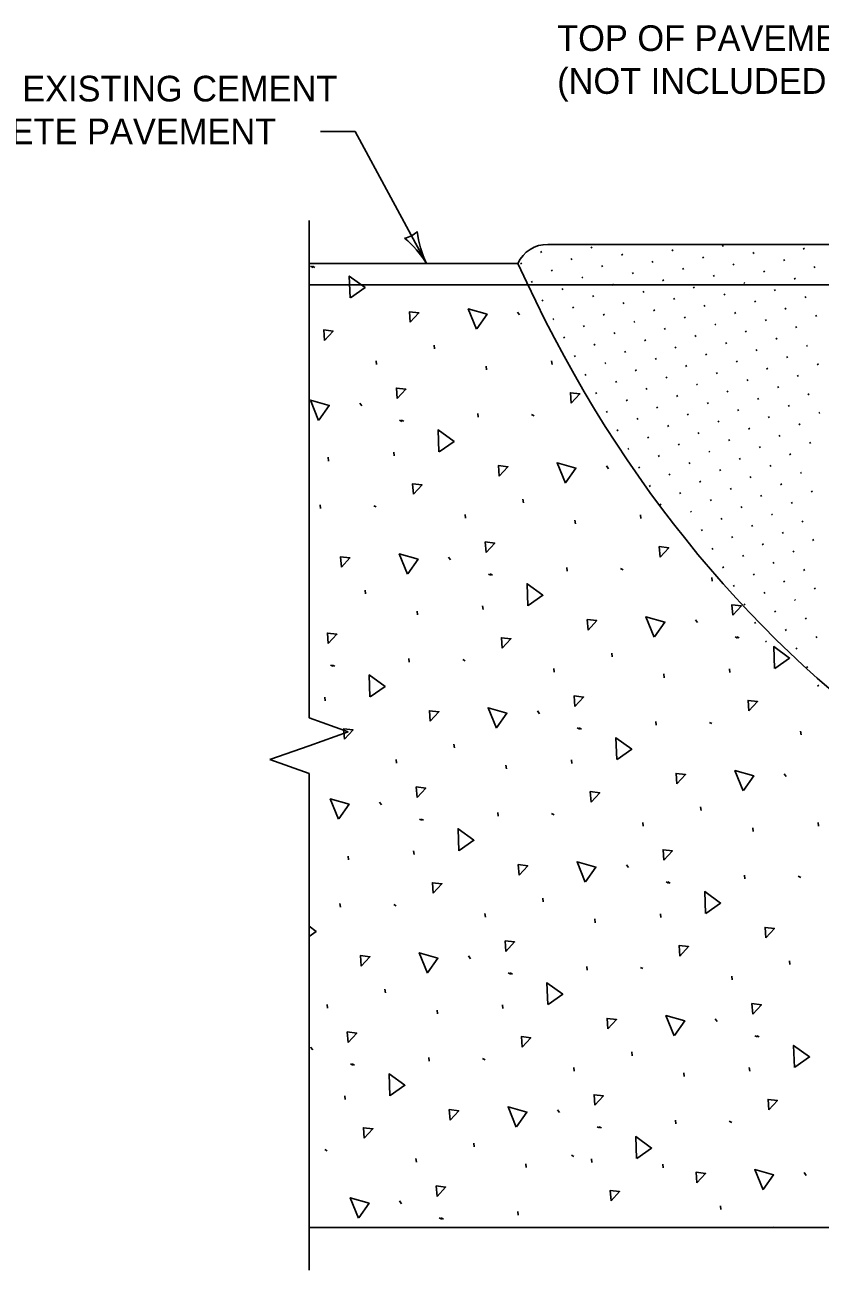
# Model space of a CAD drawing. Extents: x 49991.4 to 50021, y 49987.6 to 50011.4.
# Drawn here: x 50001.317 to 50003.173, y 49992.483 to 49995.39 of the extents above; entities that cross this region are included whole.
import ezdxf

# ---------------------------------------------------------------- set-up
doc = ezdxf.new("R2010")
doc.units = 0
for name, color, linetype in [('Level 1', 7, 'Continuous'), ('Level 2', 7, 'Continuous'), ('Level 3', 7, 'Continuous'), ('Level 4', 7, 'Continuous'), ('Level 6', 7, 'Continuous')]:
    doc.layers.add(name, color=color, linetype=linetype)

msp = doc.modelspace()

# ---------------------------------------------------------------- linework, layer by layer
at = {"layer": 'Level 1'}
for p, q in [((50002.5376, 49994.8772), (50004.5362, 49994.8772)), ((50002.4679, 49994.8328), (50001.9803, 49994.8328)), ((50008.0315, 49994.7828), (50001.9803, 49994.7828))]:
    msp.add_line(p, q, dxfattribs=at)
msp.add_lwpolyline([(50001.9803, 49992.5827), (50004.606, 49992.5827), (50014.3713, 49992.5827)], dxfattribs=at)
msp.add_arc((50002.5362, 49994.8027), 0.0746, 88.8654, 156.1576, dxfattribs=at)
msp.add_ellipse((50004.6259, 49996.2377), major_axis=(0, -2.952), ratio=0.83118, start_param=5.208402, end_param=6.283185, dxfattribs=at)
at = {"layer": 'Level 3'}
for p, q in [((50002.0877, 49995.141), (50002.0069, 49995.141)), ((50002.0877, 49995.141), (50002.2544, 49994.8328)), ((50002.9447, 49994.8729), (50002.9477, 49994.8747)), ((50002.5203, 49994.8588), (50002.5233, 49994.8606)), ((50002.638, 49994.869), (50002.641, 49994.8708)), ((50002.7093, 49994.8525), (50002.7123, 49994.8542)), ((50002.827, 49994.8627), (50002.83, 49994.8645)), ((50002.8983, 49994.8462), (50002.9014, 49994.8479)), ((50003.016, 49994.8564), (50003.019, 49994.8581)), ((50003.1337, 49994.8666), (50003.1367, 49994.8683)), ((50002.474, 49994.8321), (50002.477, 49994.8338)), ((50002.5453, 49994.8155), (50002.5483, 49994.8173)), ((50002.5916, 49994.8423), (50002.5947, 49994.844)), ((50002.663, 49994.8257), (50002.666, 49994.8275)), ((50002.7806, 49994.836), (50002.7837, 49994.8377)), ((50002.852, 49994.8194), (50002.855, 49994.8212)), ((50002.9697, 49994.8296), (50002.9727, 49994.8314)), ((50003.0873, 49994.8398), (50003.0904, 49994.8416)), ((50003.1587, 49994.8233), (50003.1617, 49994.825)), ((50002.499, 49994.7888), (50002.502, 49994.7905)), ((50002.6166, 49994.799), (50002.6197, 49994.8007)), ((50002.7343, 49994.8092), (50002.7373, 49994.8109)), ((50002.8056, 49994.7926), (50002.8087, 49994.7944)), ((50002.9233, 49994.8029), (50002.9264, 49994.8046)), ((50002.9947, 49994.7863), (50002.9977, 49994.7881)), ((50003.041, 49994.8131), (50003.044, 49994.8148)), ((50003.1123, 49994.7965), (50003.1154, 49994.7983)), ((50002.5703, 49994.7722), (50002.5733, 49994.774)), ((50002.688, 49994.7824), (50002.691, 49994.7842)), ((50002.7593, 49994.7659), (50002.7623, 49994.7676)), ((50002.877, 49994.7761), (50002.88, 49994.7779)), ((50002.9483, 49994.7596), (50002.9514, 49994.7613)), ((50003.066, 49994.7698), (50003.069, 49994.7715)), ((50002.524, 49994.7455), (50002.527, 49994.7472)), ((50002.5953, 49994.7289), (50002.5983, 49994.7307)), ((50002.6416, 49994.7557), (50002.6447, 49994.7574)), ((50002.713, 49994.7391), (50002.716, 49994.7409)), ((50002.8306, 49994.7493), (50002.8337, 49994.7511)), ((50002.902, 49994.7328), (50002.905, 49994.7346)), ((50003.0197, 49994.743), (50003.0227, 49994.7448)), ((50003.1373, 49994.7532), (50003.1404, 49994.755)), ((50002.549, 49994.7022), (50002.552, 49994.7039)), ((50002.6666, 49994.7124), (50002.6697, 49994.7141)), ((50002.7843, 49994.7226), (50002.7873, 49994.7243)), ((50002.8556, 49994.706), (50002.8587, 49994.7078)), ((50002.9733, 49994.7163), (50002.9764, 49994.718)), ((50003.0447, 49994.6997), (50003.0477, 49994.7015)), ((50003.091, 49994.7265), (50003.094, 49994.7282)), ((50003.1623, 49994.7099), (50003.1654, 49994.7117)), ((50002.6203, 49994.6856), (50002.6233, 49994.6874)), ((50002.6916, 49994.6691), (50002.6947, 49994.6708)), ((50002.738, 49994.6958), (50002.741, 49994.6976)), ((50002.8093, 49994.6793), (50002.8123, 49994.681)), ((50002.927, 49994.6895), (50002.93, 49994.6912)), ((50002.9983, 49994.673), (50003.0014, 49994.6747)), ((50003.116, 49994.6832), (50003.119, 49994.6849)), ((50002.574, 49994.6589), (50002.577, 49994.6606)), ((50002.6453, 49994.6423), (50002.6483, 49994.6441)), ((50002.763, 49994.6525), (50002.766, 49994.6543)), ((50002.8806, 49994.6627), (50002.8837, 49994.6645)), ((50002.952, 49994.6462), (50002.955, 49994.6479)), ((50003.0697, 49994.6564), (50003.0727, 49994.6582)), ((50003.141, 49994.6399), (50003.144, 49994.6416)), ((50002.599, 49994.6156), (50002.602, 49994.6173)), ((50002.7166, 49994.6258), (50002.7197, 49994.6275)), ((50002.8343, 49994.636), (50002.8373, 49994.6377)), ((50002.9056, 49994.6194), (50002.9087, 49994.6212)), ((50003.0233, 49994.6296), (50003.0264, 49994.6314)), ((50003.0947, 49994.6131), (50003.0977, 49994.6149)), ((50002.6703, 49994.599), (50002.6733, 49994.6008)), ((50002.7416, 49994.5825), (50002.7447, 49994.5842)), ((50002.788, 49994.6092), (50002.791, 49994.611)), ((50002.8593, 49994.5927), (50002.8623, 49994.5944)), ((50002.977, 49994.6029), (50002.98, 49994.6046)), ((50003.0483, 49994.5863), (50003.0514, 49994.5881)), ((50003.166, 49994.5966), (50003.169, 49994.5983)), ((50002.624, 49994.5723), (50002.627, 49994.574)), ((50002.6953, 49994.5557), (50002.6983, 49994.5575)), ((50002.813, 49994.5659), (50002.816, 49994.5677)), ((50002.9306, 49994.5761), (50002.9337, 49994.5779)), ((50003.002, 49994.5596), (50003.005, 49994.5613)), ((50003.1197, 49994.5698), (50003.1227, 49994.5716)), ((50002.649, 49994.529), (50002.652, 49994.5307)), ((50002.7666, 49994.5392), (50002.7697, 49994.5409)), ((50002.8843, 49994.5494), (50002.8873, 49994.5511)), ((50002.9556, 49994.5328), (50002.9587, 49994.5346)), ((50003.0733, 49994.543), (50003.0764, 49994.5448)), ((50003.1447, 49994.5265), (50003.1477, 49994.5282)), ((50002.7203, 49994.5124), (50002.7233, 49994.5142)), ((50002.7916, 49994.4959), (50002.7947, 49994.4976)), ((50002.838, 49994.5226), (50002.841, 49994.5244)), ((50002.9093, 49994.5061), (50002.9123, 49994.5078)), ((50003.027, 49994.5163), (50003.03, 49994.518)), ((50003.0983, 49994.4997), (50003.1014, 49994.5015)), ((50002.674, 49994.4857), (50002.677, 49994.4874)), ((50002.7453, 49994.4691), (50002.7483, 49994.4709)), ((50002.863, 49994.4793), (50002.866, 49994.4811)), ((50002.9806, 49994.4895), (50002.9837, 49994.4913)), ((50003.052, 49994.473), (50003.055, 49994.4747)), ((50003.1697, 49994.4832), (50003.1727, 49994.4849)), ((50002.699, 49994.4424), (50002.702, 49994.4441)), ((50002.8166, 49994.4526), (50002.8197, 49994.4543)), ((50002.9343, 49994.4628), (50002.9373, 49994.4645)), ((50003.0056, 49994.4462), (50003.0087, 49994.448)), ((50003.1233, 49994.4564), (50003.1264, 49994.4582)), ((50002.7703, 49994.4258), (50002.7733, 49994.4276)), ((50002.8416, 49994.4093), (50002.8447, 49994.411)), ((50002.888, 49994.436), (50002.891, 49994.4378)), ((50002.9593, 49994.4195), (50002.9623, 49994.4212)), ((50003.077, 49994.4297), (50003.08, 49994.4314)), ((50003.1483, 49994.4131), (50003.1514, 49994.4149)), ((50002.724, 49994.3991), (50002.727, 49994.4008)), ((50002.7953, 49994.3825), (50002.7983, 49994.3843)), ((50002.913, 49994.3927), (50002.916, 49994.3945)), ((50003.0306, 49994.4029), (50003.0337, 49994.4047)), ((50003.102, 49994.3864), (50003.105, 49994.3881)), ((50002.749, 49994.3558), (50002.752, 49994.3575)), ((50002.8666, 49994.366), (50002.8697, 49994.3677)), ((50002.938, 49994.3494), (50002.941, 49994.3512)), ((50002.9843, 49994.3762), (50002.9873, 49994.3779)), ((50003.0556, 49994.3596), (50003.0587, 49994.3614)), ((50002.8203, 49994.3392), (50002.8233, 49994.341)), ((50002.8916, 49994.3227), (50002.8947, 49994.3244)), ((50003.0093, 49994.3329), (50003.0123, 49994.3346)), ((50003.127, 49994.3431), (50003.13, 49994.3448)), ((50002.774, 49994.3125), (50002.777, 49994.3142)), ((50002.8453, 49994.2959), (50002.8483, 49994.2977)), ((50002.963, 49994.3061), (50002.966, 49994.3079)), ((50003.0806, 49994.3163), (50003.0837, 49994.3181)), ((50003.152, 49994.2998), (50003.155, 49994.3015)), ((50002.799, 49994.2692), (50002.802, 49994.2709)), ((50002.9166, 49994.2794), (50002.9197, 49994.2811)), ((50002.988, 49994.2628), (50002.991, 49994.2646)), ((50003.0343, 49994.2896), (50003.0373, 49994.2913)), ((50003.1056, 49994.273), (50003.1087, 49994.2748)), ((50002.8703, 49994.2526), (50002.8733, 49994.2544)), ((50002.9416, 49994.2361), (50002.9447, 49994.2378)), ((50003.0593, 49994.2463), (50003.0623, 49994.248)), ((50002.8953, 49994.2093), (50002.8983, 49994.2111)), ((50003.013, 49994.2195), (50003.016, 49994.2213)), ((50003.1306, 49994.2297), (50003.1337, 49994.2315)), ((50002.9666, 49994.1928), (50002.9697, 49994.1945)), ((50003.038, 49994.1762), (50003.041, 49994.178)), ((50003.0843, 49994.203), (50003.0873, 49994.2047)), ((50003.1556, 49994.1864), (50003.1587, 49994.1882)), ((50002.9203, 49994.166), (50002.9233, 49994.1678)), ((50002.9916, 49994.1495), (50002.9947, 49994.1512)), ((50003.1093, 49994.1597), (50003.1123, 49994.1614)), ((50002.9453, 49994.1227), (50002.9483, 49994.1245)), ((50003.063, 49994.1329), (50003.066, 49994.1347)), ((50003.0166, 49994.1062), (50003.0197, 49994.1079)), ((50003.088, 49994.0896), (50003.091, 49994.0914)), ((50003.1343, 49994.1164), (50003.1373, 49994.1181)), ((50002.9703, 49994.0794), (50002.9733, 49994.0812)), ((50003.0416, 49994.0629), (50003.0447, 49994.0646)), ((50003.1593, 49994.0731), (50003.1623, 49994.0748)), ((50002.9953, 49994.0361), (50002.9983, 49994.0379)), ((50003.113, 49994.0463), (50003.116, 49994.0481)), ((50003.0666, 49994.0196), (50003.0697, 49994.0213)), ((50003.138, 49994.003), (50003.141, 49994.0048)), ((50003.0203, 49993.9928), (50003.0233, 49993.9946)), ((50003.0916, 49993.9763), (50003.0947, 49993.978)), ((50003.0453, 49993.9495), (50003.0483, 49993.9513)), ((50003.163, 49993.9597), (50003.166, 49993.9615)), ((50003.1166, 49993.933), (50003.1197, 49993.9347)), ((50003.1416, 49993.8897), (50003.1447, 49993.8914)), ((50003.1666, 49993.8464), (50003.1697, 49993.8481))]:
    msp.add_line(p, q, dxfattribs=at)
for centre, radius, start, end in [((50002.1934, 49994.9456), 0.0548, 280.5446, 316.267), ((50002.4541, 49994.9304), 0.2223, 185.8618, 206.0453), ((50002.0552, 49994.712), 0.233, 31.2331, 50.483)]:
    msp.add_arc(centre, radius, start, end, dxfattribs=at)
at = {"layer": 'Level 4'}
for p, q in [((50001.9841, 49994.8264), (50001.9898, 49994.8236)), ((50001.9882, 49994.8264), (50001.9939, 49994.8236)), ((50002.467, 49994.7194), (50002.4718, 49994.713)), ((50002.273, 49994.6332), (50002.2721, 49994.6419)), ((50002.1379, 49994.5972), (50002.137, 49994.6059)), ((50002.3945, 49994.5844), (50002.3936, 49994.5931)), ((50002.5474, 49994.5967), (50002.5465, 49994.6053)), ((50002.0987, 49994.5068), (50002.1034, 49994.5003)), ((50002.1915, 49994.4672), (50002.1972, 49994.4643)), ((50002.1956, 49994.4672), (50002.2013, 49994.4644)), ((50002.3754, 49994.4737), (50002.3744, 49994.4824)), ((50002.4999, 49994.48), (50002.5057, 49994.4772)), ((50002.0261, 49994.3717), (50002.0252, 49994.3804)), ((50002.179, 49994.384), (50002.1781, 49994.3927)), ((50002.6744, 49994.3602), (50002.6792, 49994.3537)), ((50002.007, 49994.261), (50002.0061, 49994.2697)), ((50002.1315, 49994.2673), (50002.1373, 49994.2645)), ((50002.4805, 49994.274), (50002.4795, 49994.2827)), ((50002.3454, 49994.238), (50002.3444, 49994.2467)), ((50002.7548, 49994.2374), (50002.7539, 49994.2461)), ((50002.6019, 49994.2252), (50002.601, 49994.2339)), ((50002.3061, 49994.1475), (50002.3108, 49994.141)), ((50002.5828, 49994.1145), (50002.5819, 49994.1232)), ((50002.7073, 49994.1208), (50002.7131, 49994.1179)), ((50002.3989, 49994.1079), (50002.4046, 49994.1051)), ((50002.403, 49994.108), (50002.4087, 49994.1051)), ((50002.9211, 49994.0914), (50002.9202, 49994.1001)), ((50002.1121, 49994.0613), (50002.1111, 49994.07)), ((50002.3864, 49994.0247), (50002.3855, 49994.0334)), ((50002.2336, 49994.0125), (50002.2326, 49994.0212)), ((50002.8819, 49994.001), (50002.8866, 49993.9945)), ((50002.9747, 49993.9614), (50002.9804, 49993.9585)), ((50002.9788, 49993.9614), (50002.9845, 49993.9586)), ((50002.6879, 49993.9147), (50002.6869, 49993.9234)), ((50002.0305, 49993.8952), (50002.0363, 49993.8924)), ((50002.0346, 49993.8953), (50002.0403, 49993.8924)), ((50002.2144, 49993.9018), (50002.2135, 49993.9105)), ((50002.3389, 49993.9081), (50002.3447, 49993.9053)), ((50002.5528, 49993.8788), (50002.5518, 49993.8875)), ((50002.9622, 49993.8782), (50002.9613, 49993.8869)), ((50002.8093, 49993.8659), (50002.8084, 49993.8746)), ((50002.0181, 49993.812), (50002.0171, 49993.8207)), ((50002.5135, 49993.7883), (50002.5182, 49993.7818)), ((50002.6063, 49993.7487), (50002.6121, 49993.7459)), ((50002.6104, 49993.7487), (50002.6161, 49993.7459)), ((50002.7902, 49993.7553), (50002.7893, 49993.764)), ((50002.9147, 49993.7615), (50002.9205, 49993.7587)), ((50003.1286, 49993.7322), (50003.1276, 49993.7409)), ((50002.3195, 49993.702), (50002.3186, 49993.7107)), ((50002.1844, 49993.6661), (50002.1835, 49993.6748)), ((50002.441, 49993.6532), (50002.44, 49993.6619)), ((50002.5938, 49993.6655), (50002.5929, 49993.6742)), ((50003.0893, 49993.6417), (50003.094, 49993.6352)), ((50002.1451, 49993.5756), (50002.1498, 49993.5691)), ((50002.4218, 49993.5426), (50002.4209, 49993.5513)), ((50002.5463, 49993.5489), (50002.5521, 49993.546)), ((50002.8953, 49993.5555), (50002.8943, 49993.5642)), ((50002.2379, 49993.536), (50002.2437, 49993.5332)), ((50002.242, 49993.536), (50002.2478, 49993.5332)), ((50002.7602, 49993.5195), (50002.7592, 49993.5282)), ((50003.0168, 49993.5067), (50003.0158, 49993.5154)), ((50003.1696, 49993.5189), (50003.1687, 49993.5276)), ((50002.2255, 49993.4528), (50002.2245, 49993.4615)), ((50002.0726, 49993.4405), (50002.0717, 49993.4492)), ((50002.7209, 49993.429), (50002.7256, 49993.4226)), ((50002.9976, 49993.396), (50002.9967, 49993.4047)), ((50003.1221, 49993.4023), (50003.1279, 49993.3995)), ((50002.8137, 49993.3895), (50002.8195, 49993.3866)), ((50002.8178, 49993.3895), (50002.8235, 49993.3866)), ((50002.0534, 49993.3299), (50002.0525, 49993.3386)), ((50002.178, 49993.3362), (50002.1837, 49993.3333)), ((50002.5269, 49993.3428), (50002.526, 49993.3515)), ((50002.3918, 49993.3068), (50002.3909, 49993.3155)), ((50002.8013, 49993.3062), (50002.8003, 49993.3149)), ((50002.6484, 49993.294), (50002.6474, 49993.3027)), ((50002.3525, 49993.2163), (50002.3573, 49993.2099)), ((50002.6292, 49993.1833), (50002.6283, 49993.192)), ((50002.7537, 49993.1896), (50002.7595, 49993.1868)), ((50003.1027, 49993.1962), (50003.1018, 49993.2049)), ((50002.4453, 49993.1768), (50002.4511, 49993.1739)), ((50002.4494, 49993.1768), (50002.4552, 49993.1739)), ((50002.9676, 49993.1603), (50002.9667, 49993.169)), ((50002.1585, 49993.1301), (50002.1576, 49993.1388)), ((50002.0234, 49993.0941), (50002.0225, 49993.1028)), ((50002.4329, 49993.0936), (50002.4319, 49993.1023)), ((50002.28, 49993.0813), (50002.2791, 49993.09)), ((50002.9283, 49993.0698), (50002.933, 49993.0633)), ((50003.0211, 49993.0302), (50003.0269, 49993.0274)), ((50003.0252, 49993.0302), (50003.031, 49993.0274)), ((50001.9841, 49993.0037), (50001.9889, 49992.9972)), ((50002.7343, 49992.9835), (50002.7334, 49992.9922)), ((50002.0769, 49992.9641), (50002.0827, 49992.9612)), ((50002.081, 49992.9641), (50002.0868, 49992.9613)), ((50002.2608, 49992.9706), (50002.2599, 49992.9793)), ((50002.3854, 49992.9769), (50002.3911, 49992.9741)), ((50002.5992, 49992.9476), (50002.5983, 49992.9563)), ((50003.0087, 49992.947), (50003.0077, 49992.9557)), ((50002.8558, 49992.9347), (50002.8549, 49992.9434)), ((50002.0645, 49992.8809), (50002.0636, 49992.8896)), ((50002.5599, 49992.8571), (50002.5647, 49992.8506)), ((50002.6527, 49992.8175), (50002.6585, 49992.8147)), ((50002.6568, 49992.8175), (50002.6626, 49992.8147)), ((50002.8366, 49992.8241), (50002.8357, 49992.8328)), ((50002.9612, 49992.8304), (50002.9669, 49992.8275)), ((50002.017, 49992.7642), (50002.0227, 49992.7614)), ((50002.3659, 49992.7709), (50002.365, 49992.7796)), ((50002.2308, 49992.7349), (50002.2299, 49992.7436)), ((50002.4874, 49992.7221), (50002.4865, 49992.7308)), ((50002.5928, 49992.7509), (50002.5985, 49992.748)), ((50002.6403, 49992.7343), (50002.6394, 49992.743)), ((50002.8066, 49992.7216), (50002.8057, 49992.7303)), ((50003.1357, 49992.7106), (50003.1405, 49992.7041)), ((50002.1915, 49992.6444), (50002.1963, 49992.6379)), ((50002.4682, 49992.6114), (50002.4673, 49992.6201)), ((50002.9417, 49992.6243), (50002.9408, 49992.633)), ((50002.2844, 49992.6048), (50002.2901, 49992.602)), ((50002.2884, 49992.6049), (50002.2942, 49992.602)), ((50003.0624, 49992.5827), (50003.0623, 49992.5842))]:
    msp.add_line(p, q, dxfattribs=at)
for points in [[(50002.0761, 49994.7523), (50002.0742, 49994.8035), (50002.1113, 49994.7767), (50002.0769, 49994.7527)], [(50002.2167, 49994.6956), (50002.2149, 49994.7201), (50002.2369, 49994.7175), (50002.2167, 49994.6956)], [(50002.3712, 49994.6793), (50002.3519, 49994.7267), (50002.3959, 49994.7142), (50002.3718, 49994.6799)], [(50002.0164, 49994.6532), (50002.0145, 49994.6778), (50002.0366, 49994.6751), (50002.0164, 49994.6532)], [(50002.1861, 49994.5174), (50002.1842, 49994.5419), (50002.2063, 49994.5393), (50002.1861, 49994.5174)], [(50002.5922, 49994.5066), (50002.5903, 49994.5312), (50002.6124, 49994.5285), (50002.5922, 49994.5066)], [(50002.0028, 49994.4666), (50001.9835, 49994.514), (50002.0275, 49994.5015), (50002.0034, 49994.4672)], [(50002.2835, 49994.393), (50002.2817, 49994.4442), (50002.3187, 49994.4174), (50002.2843, 49994.3935)], [(50002.4241, 49994.3363), (50002.4223, 49994.3609), (50002.4443, 49994.3582), (50002.4241, 49994.3363)], [(50002.5786, 49994.32), (50002.5593, 49994.3675), (50002.6033, 49994.355), (50002.5792, 49994.3207)], [(50002.2238, 49994.294), (50002.2219, 49994.3185), (50002.244, 49994.3159), (50002.2238, 49994.294)], [(50002.3935, 49994.1581), (50002.3916, 49994.1827), (50002.4137, 49994.18), (50002.3935, 49994.1581)], [(50002.0558, 49994.1236), (50002.0539, 49994.1482), (50002.0759, 49994.1455), (50002.0558, 49994.1236)], [(50002.2102, 49994.1073), (50002.1909, 49994.1548), (50002.2349, 49994.1423), (50002.2108, 49994.108)], [(50002.7996, 49994.1474), (50002.7977, 49994.172), (50002.8198, 49994.1693), (50002.7996, 49994.1474)], [(50002.4909, 49994.0338), (50002.4891, 49994.085), (50002.5261, 49994.0582), (50002.4917, 49994.0342)], [(50002.9693, 49994.0116), (50002.9674, 49994.0361), (50002.9895, 49994.0335), (50002.9693, 49994.0116)], [(50002.786, 49993.9608), (50002.7667, 49994.0083), (50002.8107, 49993.9957), (50002.7866, 49993.9615)], [(50002.6316, 49993.9771), (50002.6297, 49994.0016), (50002.6517, 49993.999), (50002.6316, 49993.9771)], [(50002.0251, 49993.9455), (50002.0233, 49993.97), (50002.0453, 49993.9673), (50002.0251, 49993.9455)], [(50002.4312, 49993.9347), (50002.4294, 49993.9593), (50002.4514, 49993.9566), (50002.4312, 49993.9347)], [(50003.0667, 49993.8872), (50003.0649, 49993.9384), (50003.1019, 49993.9116), (50003.0675, 49993.8877)], [(50002.1226, 49993.8211), (50002.1207, 49993.8723), (50002.1577, 49993.8455), (50002.1233, 49993.8215)], [(50002.6009, 49993.7989), (50002.599, 49993.8235), (50002.6211, 49993.8208), (50002.6009, 49993.7989)], [(50003.007, 49993.7882), (50003.0051, 49993.8127), (50003.0272, 49993.8101), (50003.007, 49993.7882)], [(50002.2632, 49993.7644), (50002.2613, 49993.7889), (50002.2833, 49993.7863), (50002.2632, 49993.7644)], [(50002.4176, 49993.7481), (50002.3983, 49993.7956), (50002.4423, 49993.783), (50002.4182, 49993.7488)], [(50002.0628, 49993.722), (50002.061, 49993.7466), (50002.083, 49993.7439), (50002.0628, 49993.722)], [(50002.6983, 49993.6746), (50002.6965, 49993.7258), (50002.7335, 49993.6989), (50002.6991, 49993.675)], [(50002.839, 49993.6178), (50002.8371, 49993.6424), (50002.8591, 49993.6397), (50002.839, 49993.6178)], [(50002.9934, 49993.6015), (50002.9741, 49993.649), (50003.0181, 49993.6365), (50002.994, 49993.6022)], [(50002.2325, 49993.5862), (50002.2307, 49993.6108), (50002.2527, 49993.6081), (50002.2325, 49993.5862)], [(50002.6386, 49993.5755), (50002.6368, 49993.6), (50002.6588, 49993.5974), (50002.6386, 49993.5755)], [(50002.0492, 49993.5354), (50002.03, 49993.5829), (50002.0739, 49993.5703), (50002.0498, 49993.5361)], [(50002.33, 49993.4619), (50002.3281, 49993.5131), (50002.3651, 49993.4863), (50002.3307, 49993.4623)], [(50002.8083, 49993.4397), (50002.8065, 49993.4642), (50002.8285, 49993.4616), (50002.8083, 49993.4397)], [(50002.4706, 49993.4051), (50002.4687, 49993.4297), (50002.4907, 49993.427), (50002.4706, 49993.4051)], [(50002.625, 49993.3888), (50002.6058, 49993.4363), (50002.6497, 49993.4238), (50002.6256, 49993.3895)], [(50002.2702, 49993.3628), (50002.2684, 49993.3873), (50002.2904, 49993.3847), (50002.2702, 49993.3628)], [(50002.9058, 49993.3153), (50002.9039, 49993.3665), (50002.9409, 49993.3397), (50002.9065, 49993.3158)], [(50001.9803, 49993.2855), (50001.9967, 49993.2736), (50001.9803, 49993.2621)], [(50003.0464, 49993.2586), (50003.0445, 49993.2831), (50003.0665, 49993.2805), (50003.0464, 49993.2586)], [(50002.4399, 49993.227), (50002.4381, 49993.2515), (50002.4601, 49993.2489), (50002.4399, 49993.227)], [(50002.2567, 49993.1762), (50002.2374, 49993.2236), (50002.2813, 49993.2111), (50002.2572, 49993.1768)], [(50002.846, 49993.2162), (50002.8442, 49993.2408), (50002.8662, 49993.2381), (50002.846, 49993.2162)], [(50002.1022, 49993.1925), (50002.1003, 49993.217), (50002.1224, 49993.2144), (50002.1022, 49993.1925)], [(50002.5374, 49993.1026), (50002.5355, 49993.1538), (50002.5725, 49993.127), (50002.5381, 49993.1031)], [(50003.0157, 49993.0804), (50003.0139, 49993.105), (50003.0359, 49993.1023), (50003.0157, 49993.0804)], [(50002.8324, 49993.0296), (50002.8132, 49993.0771), (50002.8571, 49993.0645), (50002.833, 49993.0303)], [(50002.678, 49993.0459), (50002.6761, 49993.0705), (50002.6981, 49993.0678), (50002.678, 49993.0459)], [(50002.0716, 49993.0143), (50002.0697, 49993.0388), (50002.0917, 49993.0362), (50002.0716, 49993.0143)], [(50002.4777, 49993.0035), (50002.4758, 49993.0281), (50002.4978, 49993.0254), (50002.4777, 49993.0035)], [(50003.1132, 49992.9561), (50003.1113, 49993.0073), (50003.1483, 49992.9805), (50003.1139, 49992.9565)], [(50002.169, 49992.8899), (50002.1671, 49992.9411), (50002.2041, 49992.9143), (50002.1698, 49992.8904)], [(50002.6473, 49992.8677), (50002.6455, 49992.8923), (50002.6675, 49992.8896), (50002.6473, 49992.8677)], [(50003.0534, 49992.857), (50003.0516, 49992.8815), (50003.0736, 49992.8789), (50003.0534, 49992.857)], [(50002.3096, 49992.8332), (50002.3077, 49992.8578), (50002.3298, 49992.8551), (50002.3096, 49992.8332)], [(50002.4641, 49992.8169), (50002.4448, 49992.8644), (50002.4887, 49992.8519), (50002.4646, 49992.8176)], [(50002.1093, 49992.7909), (50002.1074, 49992.8154), (50002.1294, 49992.8128), (50002.1093, 49992.7909)], [(50002.7448, 49992.7434), (50002.7429, 49992.7946), (50002.7799, 49992.7678), (50002.7455, 49992.7438)], [(50002.8854, 49992.6867), (50002.8835, 49992.7112), (50002.9056, 49992.7086), (50002.8854, 49992.6867)], [(50003.0399, 49992.6704), (50003.0206, 49992.7178), (50003.0645, 49992.7053), (50003.0404, 49992.671)], [(50002.279, 49992.655), (50002.2771, 49992.6796), (50002.2991, 49992.6769), (50002.279, 49992.655)], [(50002.6851, 49992.6443), (50002.6832, 49992.6689), (50002.7052, 49992.6662), (50002.6851, 49992.6443)], [(50002.0957, 49992.6042), (50002.0764, 49992.6517), (50002.1204, 49992.6392), (50002.0962, 49992.6049)]]:
    msp.add_lwpolyline(points, dxfattribs=at)
at = {"layer": 'Level 6'}
for p, q in [((50001.9803, 49994.9331), (50001.9803, 49993.7718)), ((50002.0717, 49993.7394), (50001.9803, 49993.7718)), ((50002.0717, 49993.7394), (50001.9803, 49993.707)), ((50001.9803, 49993.707), (50001.8889, 49993.6746)), ((50001.9803, 49993.6422), (50001.8889, 49993.6746)), ((50001.9803, 49993.6422), (50001.9803, 49992.483))]:
    msp.add_line(p, q, dxfattribs=at)

# ---------------------------------------------------------------- texts
at = {"layer": 'Level 2'}
for s, p in [('TOP OF PAVEMENT AFTER GRINDING', (50002.5594, 49995.3288)), ('(NOT INCLUDED IN BID ITEM)', (50002.5594, 49995.2288)), ('TOP OF EXISTING CEMENT', (50000.9899, 49995.211)), ('CONCRETE PAVEMENT', (50000.9899, 49995.111))]:
    msp.add_text(s, height=0.06, dxfattribs=at).set_placement(p)

doc.saveas('drawing.dxf')
